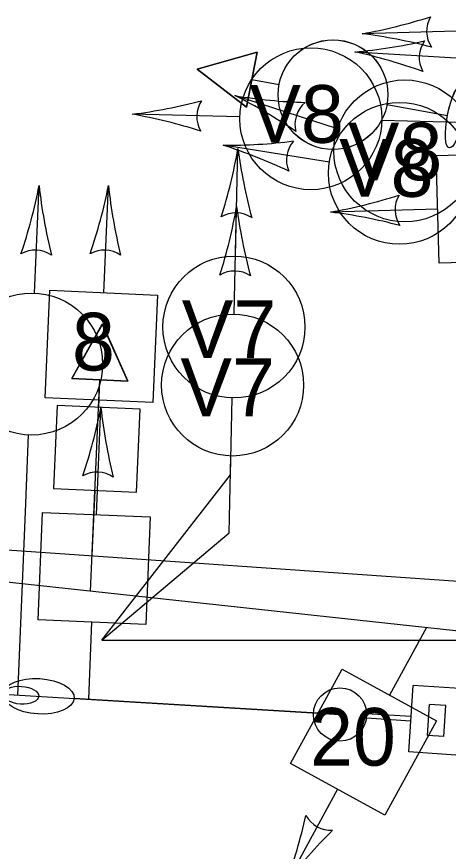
# Model space of a CAD drawing. Extents: x 647787 to 668496, y 640478 to 654412.
# Drawn here: x 662766.75 to 662791.06, y 647195.63 to 647242.66 of the extents above; entities that cross this region are included whole.
import ezdxf

# ---------------------------------------------------------------- set-up
doc = ezdxf.new("R2010")
doc.units = 0
for name, color, linetype in [('TEMP_SIGNAL POLES', 7, 'Continuous'), ('TEMP_SIGNAL_HEAD_STAGE 1A', 7, 'Continuous'), ('TEMP_SIGNAL_HEAD_STAGE 1B', 7, 'Continuous'), ('TEMP_SIGNAL_HEAD_STAGE 1C', 7, 'Continuous'), ('TEMP_SIGNAL_HEAD_STAGE 2', 7, 'Continuous'), ('TEMP_SIGNAL_HEAD_Stage 3', 7, 'Continuous'), ('TEMP_SIGNAL_HEAD_STAGE 5', 7, 'Continuous'), ('TEMP_SIGNAL_POLES_STAGE 1A', 7, 'Continuous'), ('TEMP_SIGNAL_POLES_STAGE 1B', 7, 'Continuous'), ('TEMP_SIGNAL_POLES_STAGE 1C', 7, 'Continuous'), ('TEMP_SIGNAL_POLES_STAGE 2', 7, 'Continuous'), ('TEMP_SIGNAL_POLES_STAGE 3', 7, 'Continuous'), ('TEMP_SIGNAL_POLES_STAGE 4', 7, 'Continuous'), ('TEMP_SIGNAL_POLES_STAGE 5', 7, 'Continuous'), ('TEXT_TEMP_SIGNAL_POLES_STAGE 2', 7, 'Continuous'), ('TEXT_TEMP_SIGNAL_POLES_STAGE 3', 7, 'Continuous'), ('TEXT_TEMP_SIGNAL_POLES_STAGE 4', 7, 'Continuous'), ('TEXT_TEMP_SIGNAL_POLES_STAGE 5', 7, 'Continuous')]:
    doc.layers.add(name, color=color, linetype=linetype)

msp = doc.modelspace()

# ---------------------------------------------------------------- linework, layer by layer
at = {"layer": 'TEMP_SIGNAL POLES'}
for p, q in [((662720.898, 647215.768), (662795.564, 647210.572)), ((662720.9, 647215.769), (662795.566, 647210.573))]:
    msp.add_line(p, q, dxfattribs=at)
at = {"layer": 'TEMP_SIGNAL_HEAD_STAGE 1A'}
for p, q in [((662784.811, 647236.332), (662779.044, 647238.207)), ((662779.077, 647229.17), (662779.215, 647235.233)), ((662771.651, 647227.103), (662771.917, 647233.138)), ((662771.193, 647216.703), (662771.384, 647221.046)), ((662778.796, 647216.843), (662778.894, 647221.172)), ((662771.537, 647207.519), (662778.796, 647216.843)), ((662770.91, 647210.294), (662771.193, 647216.703)), ((662789.838, 647208.244), (662787.747, 647204.433)), ((662771.537, 647207.519), (662796.537, 647207.519)), ((662788.833, 647201.222), (662789.075, 647204.964)), ((662791.985, 647204.775), (662789.075, 647204.964)), ((662789.895, 647202.155), (662790.008, 647203.901)), ((662790.923, 647203.842), (662790.008, 647203.901)), ((662790.81, 647202.096), (662790.923, 647203.842)), ((662788.946, 647202.968), (662786.445, 647203.119)), ((662788.961, 647203.217), (662786.46, 647203.369)), ((662790.81, 647202.096), (662789.895, 647202.155)), ((662791.743, 647201.033), (662788.833, 647201.222)), ((662784.829, 647199.118), (662781.923, 647193.823))]:
    msp.add_line(p, q, dxfattribs=at)
for points in [[(662780.292, 647240.653), (662779.696, 647237.553), (662776.906, 647239.696), (662780.292, 647240.653)], [(662780.294, 647240.654), (662779.699, 647237.555), (662776.908, 647239.698), (662780.294, 647240.654)], [(662781.526, 647238.808), (662779.994, 647239.103)], [(662781.528, 647238.81), (662779.996, 647239.105)], [(662787.605, 647237.711), (662791.011, 647237.096)], [(662787.608, 647237.713), (662791.013, 647237.098)], [(662773.01, 647222.124), (662769.856, 647222.263), (662771.571, 647225.335), (662773.01, 647222.124)], [(662773.012, 647222.126), (662769.859, 647222.265), (662771.574, 647225.337), (662773.012, 647222.126)], [(662771.364, 647220.635), (662771.433, 647222.193)], [(662771.367, 647220.637), (662771.435, 647222.195)], [(662770.997, 647212.306), (662771.158, 647215.96)], [(662770.999, 647212.308), (662771.16, 647215.961)]]:
    msp.add_lwpolyline(points, dxfattribs=at)
for points in [[(662776.906, 647239.696), (662779.696, 647237.553), (662780.292, 647240.653)], [(662776.908, 647239.698), (662779.699, 647237.555), (662780.294, 647240.654)], [(662774.413, 647220.913), (662768.355, 647221.18), (662768.622, 647227.237), (662774.68, 647226.97)], [(662771.571, 647225.335), (662769.856, 647222.263), (662773.01, 647222.124)], [(662771.574, 647225.337), (662769.859, 647222.265), (662773.012, 647222.126)], [(662768.82, 647216.063), (662773.496, 647215.856), (662773.702, 647220.532), (662769.026, 647220.738)], [(662768.823, 647216.064), (662773.498, 647215.858), (662773.704, 647220.534), (662769.029, 647220.74)], [(662785.089, 647205.892), (662790.405, 647202.974), (662787.487, 647197.659), (662782.171, 647200.578)]]:
    msp.add_lwpolyline(points, close=True, dxfattribs=at)
for centre, radius in [((662784.566, 647238.26), 3.089), ((662784.568, 647238.261), 3.089), ((662788.615, 647235.095), 4), ((662778.985, 647225.171), 4)]:
    msp.add_circle(centre, radius, dxfattribs=at)
for centre, radius, start, end in [((662783.855, 647267.284), 29.472, 260.6047, 268.3428), ((662765.843, 647211.86), 29.47, 55.6491, 63.3872), ((662784.053, 647236.579), 1.629, 130.1381, 193.8327), ((662750.184, 647240.302), 29.47, 342.3584, 350.0965), ((662808.447, 647238.985), 29.472, 187.314, 195.0522), ((662743, 647238.828), 29.472, 341.131, 348.8691), ((662801.224, 647236.263), 29.472, 186.0857, 193.8239), ((662779.095, 647229.968), 1.629, 56.8474, 120.542), ((662771.686, 647227.876), 1.629, 55.6301, 119.3247), ((662754.255, 647203.978), 29.472, 339.8453, 347.5834), ((662784.456, 647198.44), 1.629, 209.3897, 273.0843), ((662805.344, 647175.935), 29.472, 134.8906, 142.6287)]:
    msp.add_arc(centre, radius, start, end, dxfattribs=at)
for centre in [(662791.45, 647237.017), (662791.452, 647237.019)]:
    msp.add_ellipse(centre, major_axis=(-0.34, -1.759), ratio=0.249111, dxfattribs=at)
at = {"layer": 'TEMP_SIGNAL_HEAD_STAGE 1B'}
for p, q in [((662784.811, 647236.332), (662779.044, 647238.207)), ((662779.077, 647229.17), (662779.215, 647235.233)), ((662771.651, 647227.103), (662771.917, 647233.138)), ((662771.193, 647216.703), (662771.384, 647221.046)), ((662778.796, 647216.843), (662778.894, 647221.172)), ((662771.537, 647207.519), (662778.796, 647216.843)), ((662770.91, 647210.294), (662771.193, 647216.703)), ((662771.537, 647207.519), (662796.537, 647207.519))]:
    msp.add_line(p, q, dxfattribs=at)
for points in [[(662780.292, 647240.653), (662779.696, 647237.553), (662776.906, 647239.696), (662780.292, 647240.653)], [(662780.294, 647240.654), (662779.699, 647237.555), (662776.908, 647239.698), (662780.294, 647240.654)], [(662781.526, 647238.808), (662779.994, 647239.103)], [(662781.528, 647238.81), (662779.996, 647239.105)], [(662787.605, 647237.711), (662791.011, 647237.096)], [(662787.608, 647237.713), (662791.013, 647237.098)], [(662773.01, 647222.124), (662769.856, 647222.263), (662771.571, 647225.335), (662773.01, 647222.124)], [(662773.012, 647222.126), (662769.859, 647222.265), (662771.574, 647225.337), (662773.012, 647222.126)], [(662771.364, 647220.635), (662771.433, 647222.193)], [(662771.367, 647220.637), (662771.435, 647222.195)], [(662770.997, 647212.306), (662771.158, 647215.96)], [(662770.999, 647212.308), (662771.16, 647215.961)]]:
    msp.add_lwpolyline(points, dxfattribs=at)
for points in [[(662776.906, 647239.696), (662779.696, 647237.553), (662780.292, 647240.653)], [(662776.908, 647239.698), (662779.699, 647237.555), (662780.294, 647240.654)], [(662774.413, 647220.913), (662768.355, 647221.18), (662768.622, 647227.237), (662774.68, 647226.97)], [(662771.571, 647225.335), (662769.856, 647222.263), (662773.01, 647222.124)], [(662771.574, 647225.337), (662769.859, 647222.265), (662773.012, 647222.126)], [(662768.82, 647216.063), (662773.496, 647215.856), (662773.702, 647220.532), (662769.026, 647220.738)], [(662768.823, 647216.064), (662773.498, 647215.858), (662773.704, 647220.534), (662769.029, 647220.74)]]:
    msp.add_lwpolyline(points, close=True, dxfattribs=at)
for centre, radius in [((662784.566, 647238.26), 3.089), ((662784.568, 647238.261), 3.089), ((662788.615, 647235.095), 4), ((662778.985, 647225.171), 4)]:
    msp.add_circle(centre, radius, dxfattribs=at)
for centre, radius, start, end in [((662783.855, 647267.284), 29.472, 260.6047, 268.3428), ((662765.843, 647211.86), 29.47, 55.6491, 63.3872), ((662784.053, 647236.579), 1.629, 130.1381, 193.8327), ((662750.184, 647240.302), 29.47, 342.3584, 350.0965), ((662808.447, 647238.985), 29.472, 187.314, 195.0522), ((662743, 647238.828), 29.472, 341.131, 348.8691), ((662801.224, 647236.263), 29.472, 186.0857, 193.8239), ((662779.095, 647229.968), 1.629, 56.8474, 120.542), ((662771.686, 647227.876), 1.629, 55.6301, 119.3247)]:
    msp.add_arc(centre, radius, start, end, dxfattribs=at)
for centre in [(662791.45, 647237.017), (662791.452, 647237.019)]:
    msp.add_ellipse(centre, major_axis=(-0.34, -1.759), ratio=0.249111, dxfattribs=at)
at = {"layer": 'TEMP_SIGNAL_HEAD_STAGE 1C'}
for p, q in [((662784.811, 647236.332), (662779.044, 647238.207)), ((662779.077, 647229.17), (662779.215, 647235.233)), ((662771.651, 647227.103), (662771.917, 647233.138)), ((662771.193, 647216.703), (662771.384, 647221.046)), ((662778.796, 647216.843), (662778.894, 647221.172)), ((662771.537, 647207.519), (662778.796, 647216.843)), ((662770.91, 647210.294), (662771.193, 647216.703)), ((662771.537, 647207.519), (662796.537, 647207.519))]:
    msp.add_line(p, q, dxfattribs=at)
for points in [[(662780.292, 647240.653), (662779.696, 647237.553), (662776.906, 647239.696), (662780.292, 647240.653)], [(662780.294, 647240.654), (662779.699, 647237.555), (662776.908, 647239.698), (662780.294, 647240.654)], [(662781.526, 647238.808), (662779.994, 647239.103)], [(662781.528, 647238.81), (662779.996, 647239.105)], [(662787.605, 647237.711), (662791.011, 647237.096)], [(662787.608, 647237.713), (662791.013, 647237.098)], [(662773.01, 647222.124), (662769.856, 647222.263), (662771.571, 647225.335), (662773.01, 647222.124)], [(662773.012, 647222.126), (662769.859, 647222.265), (662771.574, 647225.337), (662773.012, 647222.126)], [(662771.364, 647220.635), (662771.433, 647222.193)], [(662771.367, 647220.637), (662771.435, 647222.195)], [(662770.997, 647212.306), (662771.158, 647215.96)], [(662770.999, 647212.308), (662771.16, 647215.961)]]:
    msp.add_lwpolyline(points, dxfattribs=at)
for points in [[(662776.906, 647239.696), (662779.696, 647237.553), (662780.292, 647240.653)], [(662776.908, 647239.698), (662779.699, 647237.555), (662780.294, 647240.654)], [(662774.413, 647220.913), (662768.355, 647221.18), (662768.622, 647227.237), (662774.68, 647226.97)], [(662771.571, 647225.335), (662769.856, 647222.263), (662773.01, 647222.124)], [(662771.574, 647225.337), (662769.859, 647222.265), (662773.012, 647222.126)], [(662768.82, 647216.063), (662773.496, 647215.856), (662773.702, 647220.532), (662769.026, 647220.738)], [(662768.823, 647216.064), (662773.498, 647215.858), (662773.704, 647220.534), (662769.029, 647220.74)]]:
    msp.add_lwpolyline(points, close=True, dxfattribs=at)
for centre, radius in [((662784.566, 647238.26), 3.089), ((662784.568, 647238.261), 3.089), ((662788.615, 647235.095), 4), ((662778.985, 647225.171), 4)]:
    msp.add_circle(centre, radius, dxfattribs=at)
for centre, radius, start, end in [((662783.855, 647267.284), 29.472, 260.6047, 268.3428), ((662765.843, 647211.86), 29.47, 55.6491, 63.3872), ((662784.053, 647236.579), 1.629, 130.1381, 193.8327), ((662750.184, 647240.302), 29.47, 342.3584, 350.0965), ((662808.447, 647238.985), 29.472, 187.314, 195.0522), ((662743, 647238.828), 29.472, 341.131, 348.8691), ((662801.224, 647236.263), 29.472, 186.0857, 193.8239), ((662779.095, 647229.968), 1.629, 56.8474, 120.542), ((662771.686, 647227.876), 1.629, 55.6301, 119.3247)]:
    msp.add_arc(centre, radius, start, end, dxfattribs=at)
for centre in [(662791.45, 647237.017), (662791.452, 647237.019)]:
    msp.add_ellipse(centre, major_axis=(-0.34, -1.759), ratio=0.249111, dxfattribs=at)
at = {"layer": 'TEMP_SIGNAL_HEAD_STAGE 2'}
for p, q in [((662784.811, 647236.332), (662779.044, 647238.207)), ((662779.077, 647229.17), (662779.215, 647235.233)), ((662771.651, 647227.103), (662771.917, 647233.138)), ((662771.193, 647216.703), (662771.384, 647221.046)), ((662778.796, 647216.843), (662778.894, 647221.172)), ((662771.537, 647207.519), (662778.796, 647216.843)), ((662770.91, 647210.294), (662771.193, 647216.703)), ((662771.537, 647207.519), (662796.537, 647207.519))]:
    msp.add_line(p, q, dxfattribs=at)
msp.add_lwpolyline([(662774.413, 647220.913), (662768.355, 647221.18), (662768.622, 647227.237), (662774.68, 647226.97)], close=True, dxfattribs=at)
for centre in [(662788.615, 647235.095), (662778.985, 647225.171)]:
    msp.add_circle(centre, 4, dxfattribs=at)
for centre, radius, start, end in [((662783.855, 647267.284), 29.472, 260.6047, 268.3428), ((662765.843, 647211.86), 29.47, 55.6491, 63.3872), ((662784.053, 647236.579), 1.629, 130.1381, 193.8327), ((662750.184, 647240.302), 29.47, 342.3584, 350.0965), ((662808.447, 647238.985), 29.472, 187.314, 195.0522), ((662743, 647238.828), 29.472, 341.131, 348.8691), ((662801.224, 647236.263), 29.472, 186.0857, 193.8239), ((662779.095, 647229.968), 1.629, 56.8474, 120.542), ((662771.686, 647227.876), 1.629, 55.6301, 119.3247)]:
    msp.add_arc(centre, radius, start, end, dxfattribs=at)
at = {"layer": 'TEMP_SIGNAL_HEAD_Stage 3'}
for p, q in [((662792.242, 647241.854), (662786.204, 647241.694)), ((662779.322, 647237.007), (662773.259, 647237.162)), ((662791.648, 647236.691), (662787.319, 647236.802)), ((662771.651, 647227.103), (662771.917, 647233.138)), ((662779.002, 647225.899), (662779.14, 647231.962)), ((662790.468, 647231.804), (662784.429, 647231.644)), ((662771.193, 647216.703), (662771.384, 647221.046)), ((662778.721, 647213.571), (662778.82, 647217.901)), ((662770.91, 647210.294), (662771.193, 647216.703)), ((662771.537, 647207.519), (662778.721, 647213.571)), ((662771.537, 647207.519), (662796.537, 647207.519))]:
    msp.add_line(p, q, dxfattribs=at)
for points in [[(662796.448, 647234.995), (662796.609, 647228.933), (662790.548, 647228.773), (662790.387, 647234.835)], [(662774.413, 647220.913), (662768.355, 647221.18), (662768.622, 647227.237), (662774.68, 647226.97)]]:
    msp.add_lwpolyline(points, close=True, dxfattribs=at)
for centre in [(662783.32, 647236.905), (662778.911, 647221.9)]:
    msp.add_circle(centre, 4, dxfattribs=at)
for centre, radius, start, end in [((662781.023, 647270.708), 29.472, 280.1232, 287.8614), ((662791.469, 647241.834), 1.629, 149.6676, 213.3623), ((662782.564, 647212.449), 29.472, 75.1685, 82.9066), ((662769.59, 647266.405), 29.472, 277.1518, 284.8899), ((662778.524, 647237.028), 1.629, 146.6852, 210.3798), ((662768.108, 647208.146), 29.47, 72.1961, 79.9342), ((662743, 647238.828), 29.472, 341.131, 348.8691), ((662801.224, 647236.263), 29.472, 186.0857, 193.8239), ((662779.249, 647260.658), 29.472, 280.1232, 287.8614), ((662789.694, 647231.784), 1.629, 149.6676, 213.3623), ((662750.109, 647237.03), 29.47, 342.3584, 350.0965), ((662808.372, 647235.714), 29.472, 187.314, 195.0522), ((662780.79, 647202.398), 29.472, 75.1685, 82.9066), ((662771.686, 647227.876), 1.629, 55.6301, 119.3247), ((662779.021, 647226.696), 1.629, 56.8474, 120.542)]:
    msp.add_arc(centre, radius, start, end, dxfattribs=at)
at = {"layer": 'TEMP_SIGNAL_HEAD_STAGE 5'}
for p, q in [((662791.824, 647240.303), (662785.795, 647240.667)), ((662784.36, 647234.459), (662778.371, 647235.413)), ((662771.651, 647227.103), (662771.917, 647233.138)), ((662779.002, 647225.899), (662779.14, 647231.962)), ((662771.193, 647216.703), (662771.384, 647221.046)), ((662778.721, 647213.571), (662778.82, 647217.901)), ((662770.91, 647210.294), (662771.193, 647216.703)), ((662771.537, 647207.519), (662778.721, 647213.571)), ((662771.537, 647207.519), (662796.537, 647207.519))]:
    msp.add_line(p, q, dxfattribs=at)
msp.add_lwpolyline([(662774.413, 647220.913), (662768.355, 647221.18), (662768.622, 647227.237), (662774.68, 647226.97)], close=True, dxfattribs=at)
for centre in [(662788.311, 647233.83), (662778.911, 647221.9)]:
    msp.add_circle(centre, 4, dxfattribs=at)
for centre, radius, start, end in [((662783.147, 647270.02), 29.472, 275.1535, 282.8917), ((662791.052, 647240.35), 1.629, 144.6979, 208.3925), ((662779.635, 647211.846), 29.472, 70.1988, 77.9369), ((662778.595, 647264.885), 29.472, 269.5654, 277.3035), ((662783.573, 647234.585), 1.629, 139.0988, 202.7934), ((662769.435, 647207.331), 29.47, 64.6097, 72.3479), ((662743, 647238.828), 29.472, 341.131, 348.8691), ((662801.224, 647236.263), 29.472, 186.0857, 193.8239), ((662750.109, 647237.03), 29.47, 342.3584, 350.0965), ((662808.372, 647235.714), 29.472, 187.314, 195.0522), ((662771.686, 647227.876), 1.629, 55.6301, 119.3247), ((662779.021, 647226.696), 1.629, 56.8474, 120.542)]:
    msp.add_arc(centre, radius, start, end, dxfattribs=at)
at = {"layer": 'TEMP_SIGNAL_POLES_STAGE 1A'}
for p, q in [((662767.758, 647227.078), (662768.011, 647233.138)), ((662771.238, 647214.592), (662771.491, 647220.627)), ((662767.242, 647214.759), (662767.423, 647219.085)), ((662719.403, 647215.872), (662796.537, 647207.519)), ((662766.811, 647204.432), (662767.242, 647214.759)), ((662770.804, 647204.191), (662770.985, 647208.534)), ((662761.001, 647204.784), (662784.96, 647203.334)), ((662784.96, 647203.334), (662769.988, 647204.24))]:
    msp.add_line(p, q, dxfattribs=at)
msp.add_lwpolyline([(662774.015, 647208.407), (662767.956, 647208.661), (662768.209, 647214.718), (662774.268, 647214.465)], close=True, dxfattribs=at)
for centre, radius in [((662767.591, 647223.082), 4), ((662784.96, 647203.334), 1.5)]:
    msp.add_circle(centre, radius, dxfattribs=at)
for centre, radius, start, end in [((662739.082, 647238.757), 29.47, 341.2689, 349.007), ((662797.31, 647236.333), 29.472, 186.2246, 193.9627), ((662767.792, 647227.875), 1.629, 55.7579, 119.4525), ((662742.561, 647226.251), 29.472, 341.2614, 348.9995), ((662800.79, 647223.818), 29.472, 186.2161, 193.9543), ((662771.272, 647215.365), 1.629, 55.7605, 119.4552)]:
    msp.add_arc(centre, radius, start, end, dxfattribs=at)
for centre, major_axis in [((662767.991, 647204.361), (-1.996, 0.121)), ((662766.993, 647204.421), (0.998, -0.06))]:
    msp.add_ellipse(centre, major_axis=major_axis, ratio=0.5, dxfattribs=at)
at = {"layer": 'TEMP_SIGNAL_POLES_STAGE 1B'}
msp.add_line((662719.403, 647215.872), (662796.537, 647207.519), dxfattribs=at)
at = {"layer": 'TEMP_SIGNAL_POLES_STAGE 1C'}
msp.add_line((662719.403, 647215.872), (662796.537, 647207.519), dxfattribs=at)
at = {"layer": 'TEMP_SIGNAL_POLES_STAGE 2'}
msp.add_line((662719.403, 647215.872), (662796.537, 647207.519), dxfattribs=at)
at = {"layer": 'TEMP_SIGNAL_POLES_STAGE 3'}
msp.add_line((662719.403, 647215.872), (662796.537, 647207.519), dxfattribs=at)
at = {"layer": 'TEMP_SIGNAL_POLES_STAGE 4'}
msp.add_line((662719.403, 647215.872), (662796.537, 647207.519), dxfattribs=at)
at = {"layer": 'TEMP_SIGNAL_POLES_STAGE 5'}
msp.add_line((662719.403, 647215.872), (662796.537, 647207.519), dxfattribs=at)

# ---------------------------------------------------------------- texts
at = {"layer": 'TEXT_TEMP_SIGNAL_POLES_STAGE 2'}
for s, p in [('V8', (662785.407, 647233.435)), ('V8', (662785.407, 647233.435)), ('V8', (662785.407, 647233.435)), ('V8', (662785.407, 647233.435)), ('V7', (662776.049, 647223.417)), ('V7', (662776.049, 647223.417)), ('V7', (662776.049, 647223.417)), ('V7', (662776.049, 647223.417)), ('8', (662769.864, 647222.72)), ('8', (662769.864, 647222.72)), ('8', (662769.864, 647222.72)), ('8', (662769.864, 647222.72)), ('20', (662783.273, 647200.452))]:
    msp.add_text(s, height=3.25, dxfattribs=at).set_placement(p)
at = {"layer": 'TEXT_TEMP_SIGNAL_POLES_STAGE 3'}
for s, p in [('V8', (662779.86, 647235.55)), ('8', (662769.864, 647222.72)), ('V7', (662775.975, 647220.146))]:
    msp.add_text(s, height=3.25, dxfattribs=at).set_placement(p)
at = {"layer": 'TEXT_TEMP_SIGNAL_POLES_STAGE 4'}
for s, p in [('V8', (662779.86, 647235.55)), ('8', (662769.864, 647222.72)), ('V7', (662775.975, 647220.146))]:
    msp.add_text(s, height=3.25, dxfattribs=at).set_placement(p)
at = {"layer": 'TEXT_TEMP_SIGNAL_POLES_STAGE 5'}
for s, p in [('V8', (662784.914, 647232.508)), ('8', (662769.864, 647222.72)), ('V7', (662775.975, 647220.146))]:
    msp.add_text(s, height=3.25, dxfattribs=at).set_placement(p)

doc.saveas('drawing.dxf')
